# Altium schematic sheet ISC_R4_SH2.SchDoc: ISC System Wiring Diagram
size C; DrawnBy: Filiberto Clara; Engineer: Filiberto Clara; Organization: LIGO Laboratory; Address1: California Institute of Technology; Address2: Massachusetts Institute of Technology; SheetNumber: 16; SheetTotal: 39
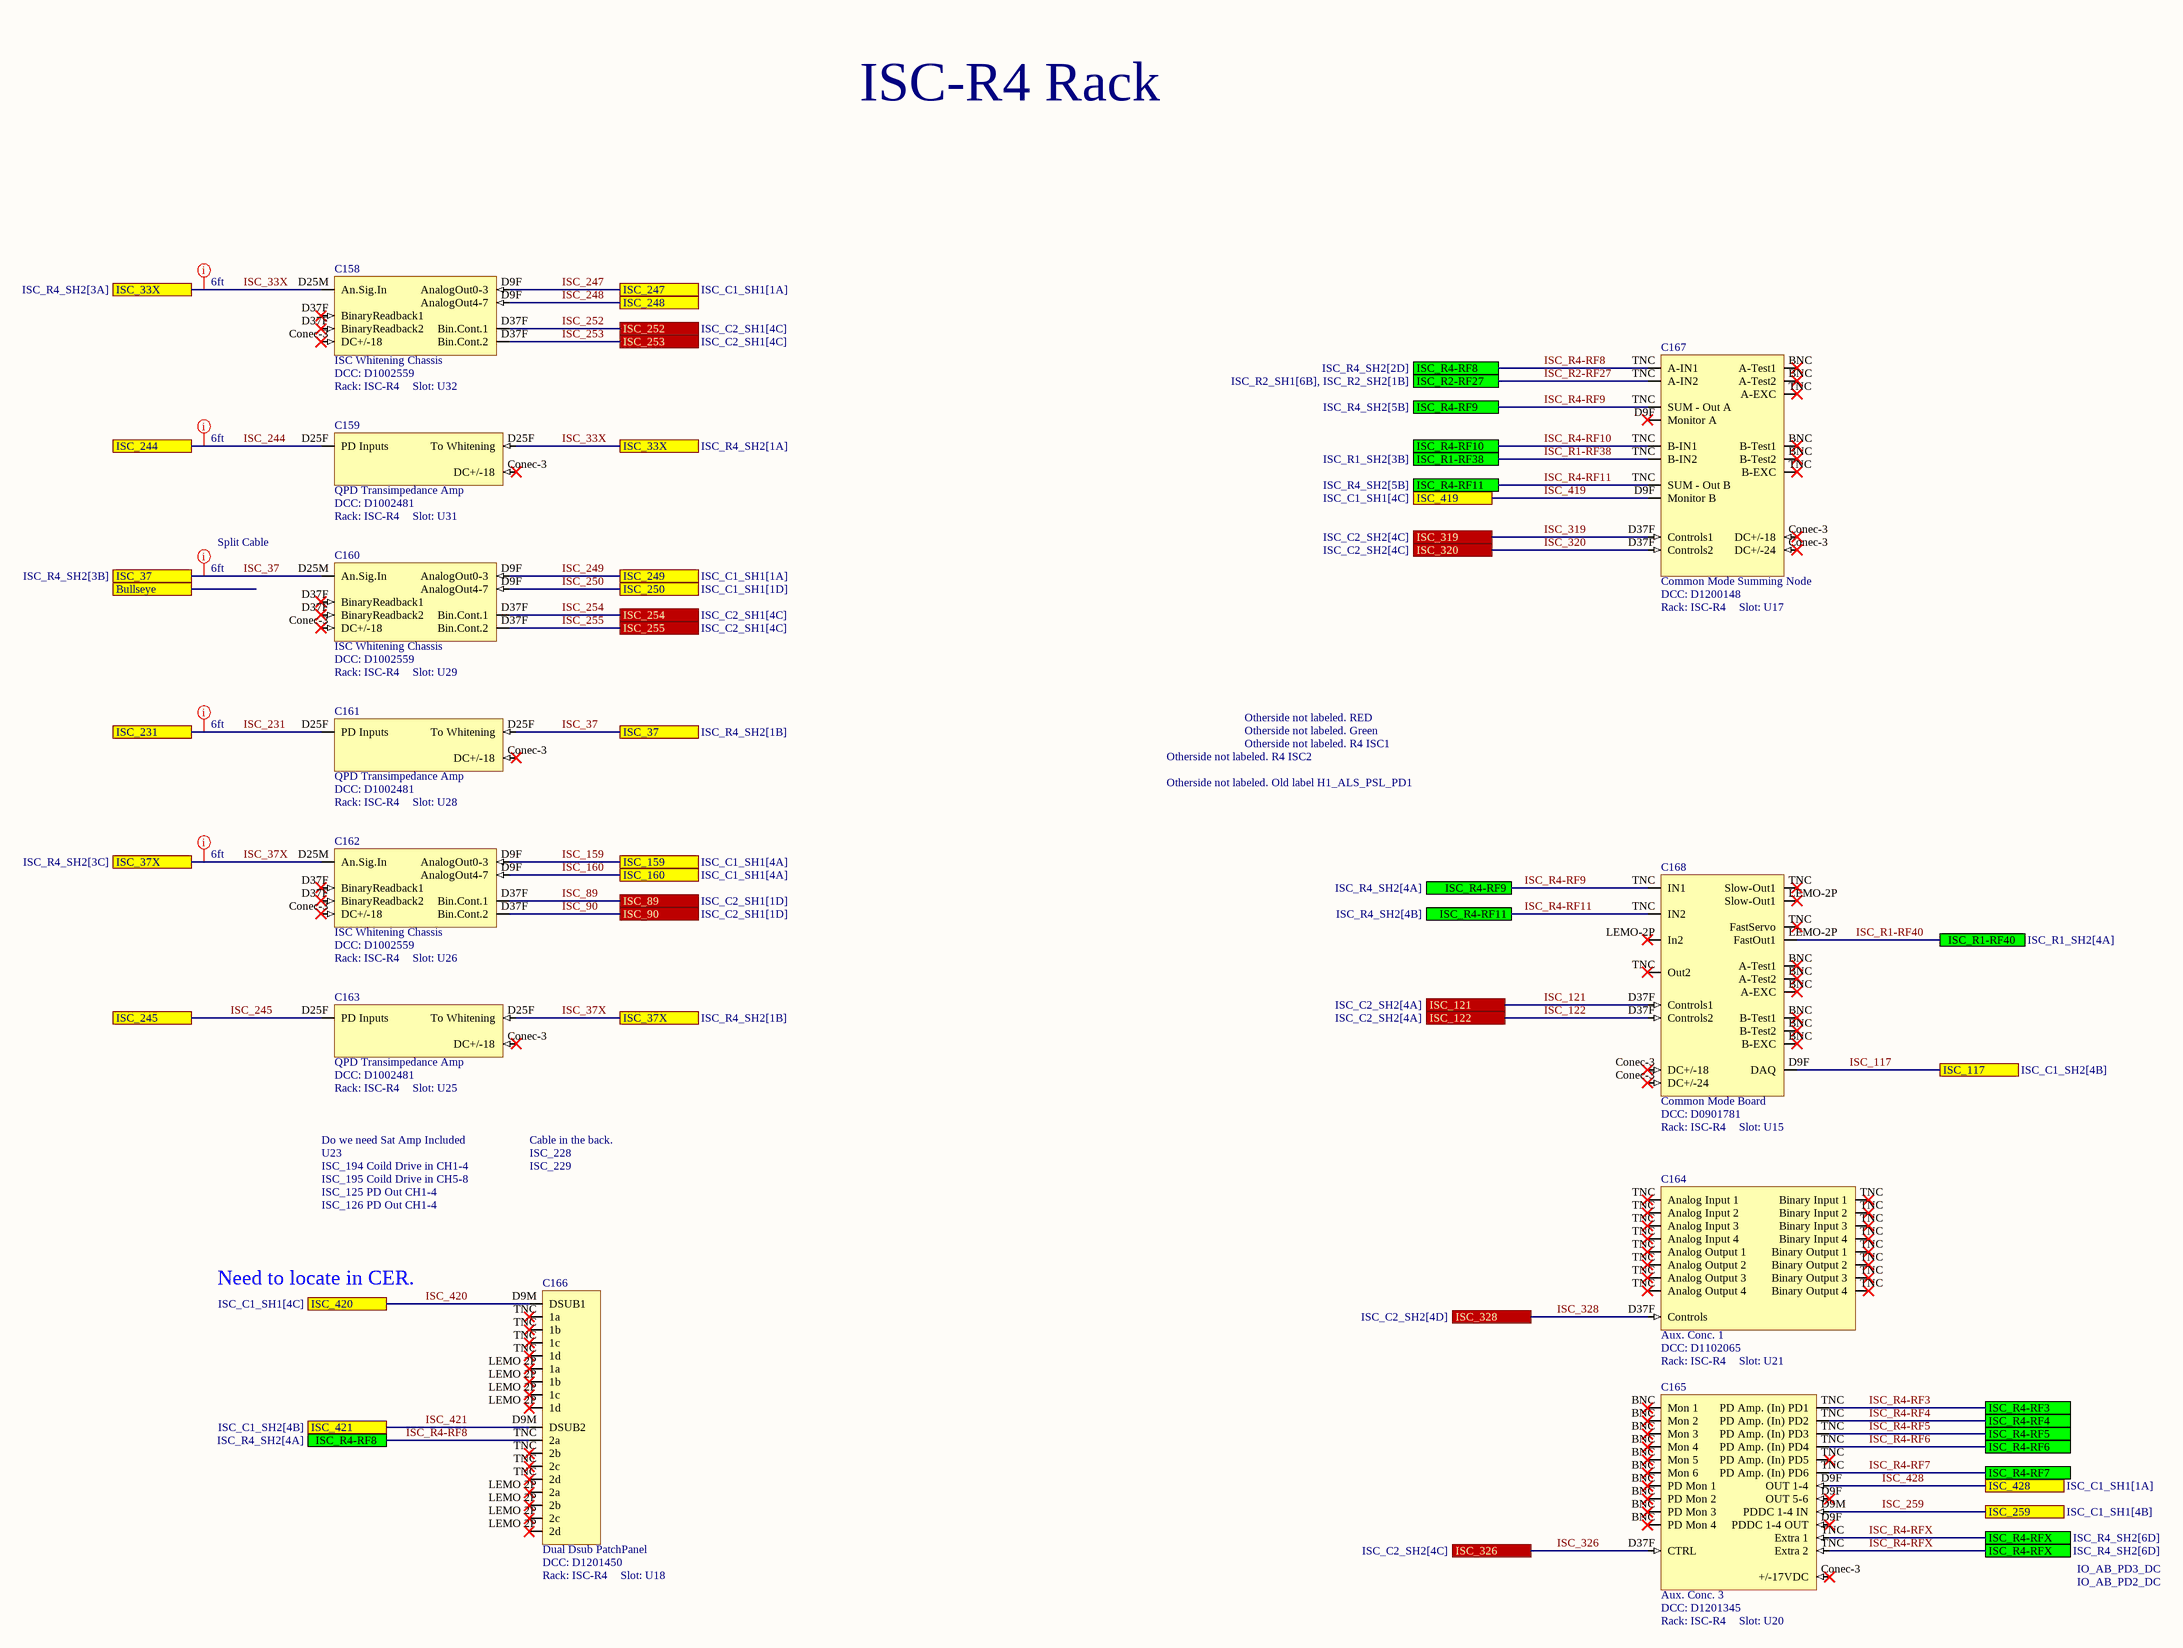
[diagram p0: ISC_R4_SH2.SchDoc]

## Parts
C158  ISC Whitening Chassis  DCC: D1002559  Rack: ISC-R4  Slot: U32
C159  QPD Transimpedance Amp  DCC: D1002481  Rack: ISC-R4  Slot: U31
C160  ISC Whitening Chassis  DCC: D1002559  Rack: ISC-R4  Slot: U29
C161  QPD Transimpedance Amp  DCC: D1002481  Rack: ISC-R4  Slot: U28
C162  ISC Whitening Chassis  DCC: D1002559  Rack: ISC-R4  Slot: U26
C163  QPD Transimpedance Amp  DCC: D1002481  Rack: ISC-R4  Slot: U25
C164  Aux. Conc. 1  DCC: D1102065  Rack: ISC-R4  Slot: U21
C165  Aux. Conc. 3  DCC: D1201345  Rack: ISC-R4  Slot: U20
C166  Dual Dsub PatchPanel  DCC: D1201450  Rack: ISC-R4  Slot: U18
C167  Common Mode Summing Node  DCC: D1200148  Rack: ISC-R4  Slot: U17
C168  Common Mode Board  DCC: D0901781  Rack: ISC-R4  Slot: U15

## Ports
Bullseye, ISC_33X (see ISC_R4_SH2[1A]), ISC_33X (see ISC_R4_SH2[3A]), ISC_37 (see ISC_R4_SH2[1B]), ISC_37 (see ISC_R4_SH2[3B]), ISC_37X (see ISC_R4_SH2[1B]), ISC_37X (see ISC_R4_SH2[3C]), ISC_89 (see ISC_C2_SH1[1D]), ISC_90 (see ISC_C2_SH1[1D]), ISC_117 (see ISC_C1_SH2[4B]), ISC_121 (see ISC_C2_SH2[4A]), ISC_122 (see ISC_C2_SH2[4A]), ISC_159 (see ISC_C1_SH1[4A]), ISC_160 (see ISC_C1_SH1[4A]), ISC_231, ISC_244, ISC_245, ISC_247 (see ISC_C1_SH1[1A]), ISC_248, ISC_249 (see ISC_C1_SH1[1A]), ISC_250 (see ISC_C1_SH1[1D]), ISC_252 (see ISC_C2_SH1[4C]), ISC_253 (see ISC_C2_SH1[4C]), ISC_254 (see ISC_C2_SH1[4C]), ISC_255 (see ISC_C2_SH1[4C]), ISC_259 (see ISC_C1_SH1[4B]), ISC_319 (see ISC_C2_SH2[4C]), ISC_320 (see ISC_C2_SH2[4C]), ISC_326 (see ISC_C2_SH2[4C]), ISC_328 (see ISC_C2_SH2[4D]), ISC_419 (see ISC_C1_SH1[4C]), ISC_420 (see ISC_C1_SH1[4C]), ISC_421 (see ISC_C1_SH2[4B]), ISC_428 (see ISC_C1_SH1[1A]), ISC_R1-RF38 (see ISC_R1_SH2[3B]), ISC_R1-RF40 (see ISC_R1_SH2[4A]), ISC_R2-RF27 (see ISC_R2_SH1[6B], ISC_R2_SH2[1B]), ISC_R4-RF3, ISC_R4-RF4, ISC_R4-RF5, ISC_R4-RF6, ISC_R4-RF7, ISC_R4-RF8 (see ISC_R4_SH2[2D]), ISC_R4-RF8 (see ISC_R4_SH2[4A]), ISC_R4-RF9 (see ISC_R4_SH2[4A]), ISC_R4-RF9 (see ISC_R4_SH2[5B]), ISC_R4-RF10, ISC_R4-RF11 (see ISC_R4_SH2[4B]), ISC_R4-RF11 (see ISC_R4_SH2[5B]), ISC_R4-RFX (see ISC_R4_SH2[6D])

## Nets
ISC_33X: C158.D25M(An.Sig.In) C159.D25F(To_Whitening) ; port ISC_33X
ISC_37: C160.D25M(An.Sig.In) C161.D25F(To_Whitening) ; port ISC_37
ISC_37X: C162.D25M(An.Sig.In) C163.D25F(To_Whitening) ; port ISC_37X
ISC_89: C162.D37F(BinaryReadback1) ; port ISC_89
ISC_90: C162.D37F(Bin.Cont.2) ; port ISC_90
ISC_117: C168.D9F(DAQ) ; port ISC_117
ISC_121: C168.D37F(Controls1) ; port ISC_121
ISC_122: C168.D37F(Controls2) ; port ISC_122
ISC_159: C162.D9F(AnalogOut0-3) ; port ISC_159
ISC_160: C162.D9F(AnalogOut4-7) ; port ISC_160
ISC_231: C161.D25F(PD_Inputs) ; port ISC_231
ISC_244: C159.D25F(PD_Inputs) ; port ISC_244
ISC_245: C163.D25F(PD_Inputs) ; port ISC_245
ISC_247: C158.D9F(AnalogOut0-3) ; port ISC_247
ISC_248: C158.D9F(AnalogOut4-7) ; port ISC_248
ISC_249: C160.D9F(AnalogOut0-3) ; port ISC_249
ISC_250: C160.D9F(AnalogOut4-7) ; port ISC_250
ISC_252: C158.D37F(BinaryReadback1) ; port ISC_252
ISC_253: C158.D37F(Bin.Cont.2) ; port ISC_253
ISC_254: C160.D37F(BinaryReadback1) ; port ISC_254
ISC_255: C160.D37F(Bin.Cont.2) ; port ISC_255
ISC_259: C165.D9M(PDDC_1-4_IN) ; port ISC_259
ISC_319: C167.D37F(Controls1) ; port ISC_319
ISC_320: C167.D37F(Controls2) ; port ISC_320
ISC_326: C165.D37F(CTRL) ; port ISC_326
ISC_328: C164.D37F(Controls) ; port ISC_328
ISC_419: C167.D9F(Monitor_A) ; port ISC_419
ISC_420: C166.D9M(DSUB1) ; port ISC_420
ISC_421: C166.D9M(DSUB2) ; port ISC_421
ISC_428: C165.D9F(PDDC_1-4_OUT) ; port ISC_428
ISC_R1-RF38: C167.TNC(B-IN2) ; port ISC_R1-RF38
ISC_R1-RF40: C168.LEMO-2P(In2) ; port ISC_R1-RF40
ISC_R2-RF27: C167.TNC(A-IN2) ; port ISC_R2-RF27
ISC_R4-RF3: C165.TNC(PD_Amp._(In)_PD1) ; port ISC_R4-RF3
ISC_R4-RF4: C165.TNC(PD_Amp._(In)_PD2) ; port ISC_R4-RF4
ISC_R4-RF5: C165.TNC(PD_Amp._(In)_PD3) ; port ISC_R4-RF5
ISC_R4-RF6: C165.TNC(PD_Amp._(In)_PD4) ; port ISC_R4-RF6
ISC_R4-RF7: C165.TNC(PD_Amp._(In)_PD6) ; port ISC_R4-RF7
ISC_R4-RF8: C166.TNC(1a) C167.TNC(A-IN1) ; port ISC_R4-RF8
ISC_R4-RF9: C167.TNC(SUM_-_Out_A) C168.TNC(IN1) ; port ISC_R4-RF9
ISC_R4-RF10: C167.TNC(B-IN1) ; port ISC_R4-RF10
ISC_R4-RF11: C167.TNC(SUM_-_Out_B) C168.TNC(IN2) ; port ISC_R4-RF11
ISC_R4-RFX: C165.TNC(Extra_1) ; port ISC_R4-RFX

Not connected (* = marked no-connect by the designer): C158 Conec-3(DC+/-18)*; C159 Conec-3(DC+/-18)*; C160 Conec-3(DC+/-18)*; C161 Conec-3(DC+/-18)*; C162 Conec-3(DC+/-18)*; C163 Conec-3(DC+/-18)*; C164 TNC(Analog_Input_1)*; C165 BNC(PD_Mon_1)* Conec-3(+/-17VDC)*; C166 LEMO 2P(1a)*; C167 BNC(A-Test1)* Conec-3(DC+/-18)*; C168 BNC(A-Test1)* Conec-3(DC+/-18)*

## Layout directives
Length: 6ft: ISC_33X, ISC_37, ISC_37X, ISC_231, ISC_244

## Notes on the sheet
- ISC-R4 Rack
- Split Cable
- Otherside not labeled. R4 ISC2
- Otherside not labeled. RED
- Otherside not labeled. Green
- Otherside not labeled. R4 ISC1
- Otherside not labeled. Old label H1_ALS_PSL_PD1
- Do we need Sat Amp Included
- U23
- Cable in the back.
- ISC_228
- ISC_194 Coild Drive in CH1-4
- ISC_195 Coild Drive in CH5-8
- ISC_125 PD Out CH1-4
- ISC_126 PD Out CH1-4
- ISC_229
- Need to locate in CER.
- IO_AB_PD3_DC
- IO_AB_PD2_DC

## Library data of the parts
C158 C160 C162 = ISC Whitening: Serial: Sxxxxxxx
C159 C161 C163 = QPD Transimpedance Amp: Serial: Sxxxxxxx; System: ISC
C164 = Aux. Conc. 1: Serial: Sxxxxxxx; System: ISC
C165 = Aux. Conc. 3: Serial: Sxxxxxxx; System: ISC
C166 = Dual Dsub PatchPanel: Serial: Sxxxxxxx; System: ISC
C167 = Common Mode Summing Node: Serial: Sxxxxxxx; System: ISC
C168 = CommonModeBoard: Serial: Sxxxxxxx; System: ISC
